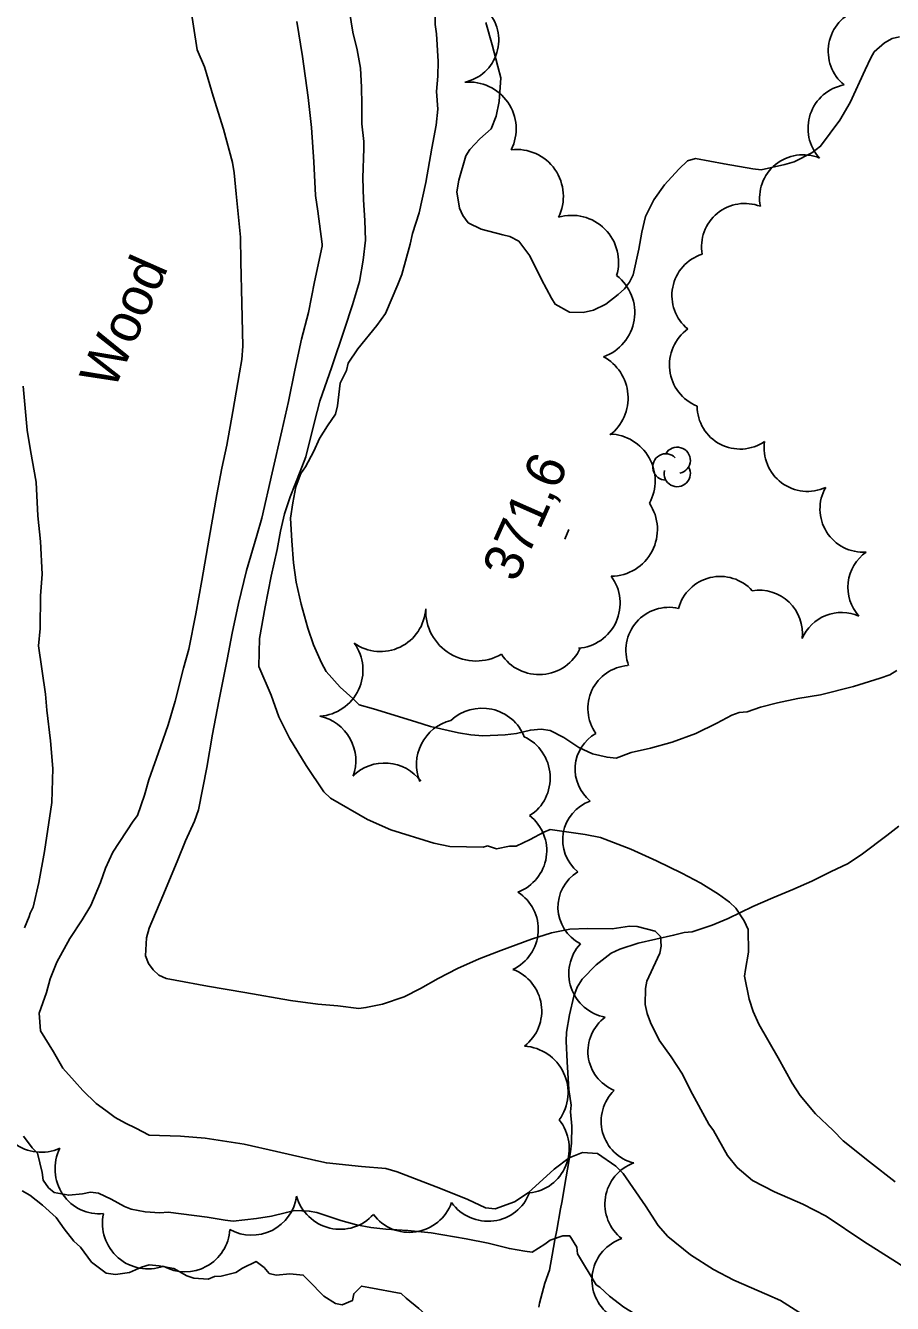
# Model space of a CAD drawing. Extents: x 287698 to 290158, y 5234163 to 5237182.
# Drawn here: x 288877.3 to 288944.5, y 5235304.2 to 5235403.1 of the extents above; entities that cross this region are included whole.
import ezdxf

# ---------------------------------------------------------------- set-up
doc = ezdxf.new("R2010")
doc.units = 0
for name, color, linetype in [('Niveau 1', 7, 'Continuous'), ('Niveau 2', 7, 'Continuous'), ('Niveau 3', 7, 'Continuous'), ('Niveau 4', 7, 'Continuous'), ('Niveau 44', 7, 'Continuous')]:
    doc.layers.add(name, color=color, linetype=linetype)

msp = doc.modelspace()

# ---------------------------------------------------------------- linework, layer by layer
at = {"layer": 'Niveau 1'}
for points in [[(288909.03, 5235404.38), (288909.07, 5235403.22), (288909.16, 5235402.51), (288909.29, 5235400.36), (288909.28, 5235399.23), (288909.16, 5235398.04), (288909.26, 5235396.66), (288909.13, 5235395.43), (288908.81, 5235393.65), (288908.33, 5235390.99), (288907.82, 5235388.64), (288907.3, 5235387.04), (288907.13, 5235386.21), (288906.49, 5235383.85), (288906.18, 5235383.08), (288905.23, 5235380.85), (288904.54, 5235379.92), (288903.08, 5235378.09), (288902.33, 5235377), (288902.2, 5235376.42), (288901.7, 5235375.44), (288901.7, 5235375.44)], [(288901.34, 5235373.04), (288901.51, 5235373.7), (288901.7, 5235375.44), (288901.7, 5235375.44)], [(288944.81, 5235353.19), (288944.27, 5235352.86), (288943.53, 5235352.59), (288941.47, 5235351.96), (288938.91, 5235351.31), (288937.16, 5235351.01), (288935.57, 5235350.68), (288934.26, 5235350.34), (288933.22, 5235349.98), (288932.62, 5235349.94), (288932.05, 5235349.72), (288930.89, 5235349.11), (288929.25, 5235348.32), (288927.42, 5235347.65), (288925.74, 5235347.17), (288924.25, 5235346.83), (288923.08, 5235346.4), (288922.38, 5235346.47), (288921.25, 5235346.73), (288920.2, 5235347.22), (288919.02, 5235347.99), (288917.98, 5235348.54), (288917.28, 5235348.64), (288916.44, 5235348.57), (288915.36, 5235348.31), (288914.49, 5235348.22), (288912.75, 5235348.14), (288911.82, 5235348.21), (288910.88, 5235348.37), (288908.71, 5235348.86), (288907.56, 5235349.22), (288904.28, 5235350.21), (288903.18, 5235350.54), (288902.7, 5235351.03), (288901.71, 5235351.9), (288900.63, 5235353.12), (288900.26, 5235353.78), (288899.63, 5235355.19), (288899.21, 5235356.48), (288898.68, 5235358.34), (288898.29, 5235360.03), (288898.09, 5235361.53), (288897.96, 5235363.22), (288897.87, 5235365), (288898.03, 5235366.17), (288898.27, 5235367.41), (288898.66, 5235368.46), (288899.01, 5235368.97), (288899.67, 5235370.17), (288900.11, 5235371.15), (288900.73, 5235372.14), (288901.34, 5235373.04)]]:
    msp.add_lwpolyline(points, dxfattribs=at)
at = {"layer": 'Niveau 2'}
for points in [[(288871.42, 5235442.49), (288871.8, 5235441.74), (288873.64, 5235438.07), (288875.41, 5235434.48), (288877.8, 5235431.27), (288880.18, 5235427.92), (288882.5, 5235424.24), (288884.58, 5235420.73), (288886.58, 5235416.8), (288888.1, 5235412.89), (288889.18, 5235408.93), (288890.06, 5235404.93), (288890.62, 5235401.27)], [(288902.27, 5235405.22), (288902.7, 5235402.62), (288903.03, 5235401.25), (288903.28, 5235399.83), (288903.37, 5235398.37), (288903.39, 5235397.03), (288903.39, 5235395.52)], [(288898.35, 5235403.46), (288898.78, 5235400.75), (288899.23, 5235397.58), (288899.49, 5235395.25), (288899.67, 5235392.59), (288899.8, 5235389.99), (288899.97, 5235388.76), (288900.32, 5235386.21), (288900.3, 5235386.06)], [(288945.02, 5235402.26), (288944.47, 5235402.13), (288943.86, 5235401.81), (288943.07, 5235401.1), (288942.8, 5235400.64), (288942.37, 5235399.7), (288941.2, 5235397.18), (288940.41, 5235395.82), (288938.91, 5235393.79), (288938.23, 5235393.28), (288936.87, 5235392.58), (288936.15, 5235392.39), (288934.31, 5235391.96), (288933.67, 5235392.05), (288931.44, 5235392.42), (288929.22, 5235392.84), (288928.62, 5235392.66), (288927.94, 5235392.03), (288926.83, 5235390.8), (288926, 5235389.63), (288925.36, 5235388.34), (288925.07, 5235387.13), (288924.84, 5235385.83), (288924.39, 5235383.84), (288924.12, 5235383.26), (288923.72, 5235382.74), (288923.24, 5235382.31), (288922.28, 5235381.55), (288921.32, 5235381.11), (288920.54, 5235380.92), (288919.47, 5235380.95), (288918.36, 5235381.55), (288918.08, 5235382.03), (288917.31, 5235383.46), (288916.4, 5235385.31), (288915.54, 5235386.43), (288914.85, 5235386.8), (288914.31, 5235386.92), (288912.62, 5235387.36), (288911.63, 5235387.87), (288911.22, 5235388.43), (288910.96, 5235388.99), (288910.75, 5235390.26), (288910.91, 5235391.17), (288911.43, 5235393.05), (288911.76, 5235393.54), (288912.53, 5235394.36), (288913.4, 5235395.14), (288913.8, 5235396.12), (288914.02, 5235397.26), (288914.14, 5235399.09), (288913.93, 5235399.98), (288913.49, 5235401.64), (288912.98, 5235403.37)], [(288890.62, 5235401.27), (288891.19, 5235399.94), (288891.36, 5235399.42), (288891.88, 5235397.66), (288892.66, 5235395.12), (288893.37, 5235392.54), (288893.49, 5235391.73), (288893.65, 5235390.1), (288893.98, 5235386.76), (288894.02, 5235384.83), (288894.09, 5235381.64), (288894.17, 5235378.32), (288894.09, 5235377.27), (288893.92, 5235376.24), (288893.39, 5235373.24), (288892.93, 5235370.65), (288892.55, 5235368.85), (288892.16, 5235366.81), (288891.57, 5235363.45), (288890.99, 5235360.17), (288890.53, 5235357.57), (288889.99, 5235354.84), (288889.58, 5235353.36), (288888.92, 5235350.82), (288888.38, 5235348.98), (288887.79, 5235347.28), (288886.9, 5235344.73), (288886.55, 5235343.53), (288886.02, 5235341.97), (288885.68, 5235341.51), (288884.09, 5235339.13), (288883.53, 5235337.89), (288883.14, 5235336.76), (288882.4, 5235334.98), (288881.73, 5235333.89), (288880.77, 5235332.43), (288879.76, 5235330.61), (288879.24, 5235329.3), (288878.95, 5235328.25), (288878.4, 5235326.64), (288878.4, 5235326.64)], [(288903.39, 5235395.52), (288903.53, 5235394.17), (288903.53, 5235393.62), (288903.46, 5235391.35), (288903.52, 5235389.64), (288903.63, 5235388.05), (288903.67, 5235386.52), (288903.5, 5235384.96), (288903.2, 5235383.32), (288902.66, 5235381.51), (288902.04, 5235379.62), (288901.05, 5235376.71), (288900.12, 5235374.05), (288899.72, 5235372.44), (288899.05, 5235369.74), (288898.62, 5235368.59), (288897.84, 5235366.64), (288897.39, 5235365.32), (288897.08, 5235363.99), (288896.83, 5235362.57), (288896.37, 5235360.49), (288895.9, 5235358.11), (288895.47, 5235355.67), (288895.4, 5235353.51), (288895.4, 5235353.51)], [(288900.3, 5235386.06), (288899.71, 5235383.29), (288899.25, 5235380.91), (288898.72, 5235378.85), (288898.19, 5235376.45), (288897.7, 5235374.02), (288897.18, 5235371.76), (288896.44, 5235368.51), (288895.63, 5235364.98), (288895.24, 5235363.64), (288894.46, 5235360.94), (288893.82, 5235358.37), (288893.33, 5235356.09), (288892.96, 5235354.05), (288892.32, 5235350.81), (288891.83, 5235348.26), (288891.38, 5235345.69), (288890.74, 5235342.41), (288890.43, 5235341.53), (288889.73, 5235340), (288889.08, 5235338.4), (288887.96, 5235335.73), (288886.91, 5235333.23), (288886.71, 5235332.48), (288886.64, 5235331.08), (288886.86, 5235330.5), (288887.22, 5235330), (288887.67, 5235329.6), (288888.24, 5235329.33), (288888.94, 5235329.2), (288891.44, 5235328.74), (288894.33, 5235328.25), (288897.87, 5235327.62), (288899.97, 5235327.35), (288901.53, 5235327.22), (288903.15, 5235327.01), (288903.7, 5235327.08), (288904.99, 5235327.36), (288906.67, 5235327.91), (288907.94, 5235328.57), (288909.29, 5235329.34), (288910.79, 5235330.12), (288912.46, 5235330.85), (288914.16, 5235331.51), (288916.53, 5235332.38), (288918.08, 5235332.88), (288919.5, 5235333.16), (288920.86, 5235333.2), (288922.77, 5235333.19), (288924.12, 5235333.38), (288924.72, 5235333.37), (288926.1, 5235333), (288926.51, 5235332.58), (288926.56, 5235331.84), (288926.46, 5235331.31), (288925.96, 5235330.2), (288925.46, 5235329.13), (288925.36, 5235328.55), (288925.32, 5235327.31), (288925.48, 5235326.62), (288925.75, 5235325.94), (288926.41, 5235324.57), (288927.34, 5235323.26), (288928.23, 5235321.92), (288928.83, 5235320.66), (288930.27, 5235318.06), (288930.61, 5235317.56)], [(288877.61, 5235334.14), (288877.7, 5235334.4), (288877.93, 5235334.87), (288878.36, 5235336.78), (288878.8, 5235339.16), (288879.37, 5235342.98), (288879.46, 5235345.6), (288879.27, 5235347.74), (288878.99, 5235350.11), (288878.88, 5235351.37), (288878.33, 5235355.09), (288878.47, 5235356.44), (288878.5, 5235358.98), (288878.63, 5235360.64), (288878.5, 5235363.18), (288878.3, 5235365.16), (288878.17, 5235367.77), (288877.72, 5235370.22), (288877.46, 5235371.8), (288877.16, 5235375.21)], [(288913.13, 5235339.61), (288912.79, 5235339.52), (288910.21, 5235339.57), (288908.96, 5235339.82), (288905.64, 5235340.84), (288903.82, 5235341.64), (288900.97, 5235343.29), (288900.43, 5235343.79), (288899.07, 5235345.83), (288897.78, 5235347.95), (288896.95, 5235349.6), (288896.36, 5235351.27), (288895.4, 5235353.51)], [(288944.7, 5235313.6), (288942.7, 5235315.13), (288940.67, 5235316.77), (288939.88, 5235317.56), (288938.52, 5235318.85), (288937.33, 5235320.28), (288936.71, 5235321.22), (288935.63, 5235323.18), (288934.14, 5235325.8), (288933.7, 5235326.77), (288933.39, 5235327.74), (288933.03, 5235329.51), (288933.1, 5235330.04), (288933.34, 5235331.38), (288933.32, 5235333.13), (288932.99, 5235333.8), (288932.34, 5235334.79), (288931.85, 5235335.26), (288931, 5235335.88), (288929.63, 5235336.73), (288928.18, 5235337.49), (288926.22, 5235338.45), (288924.22, 5235339.35), (288921.86, 5235340.25), (288920.67, 5235340.48), (288917.97, 5235340.88), (288917.49, 5235340.66), (288916.43, 5235340.09), (288915.35, 5235339.59), (288914.82, 5235339.58), (288913.81, 5235339.39), (288913.13, 5235339.61)], [(288877.27, 5235333.26), (288877.61, 5235334.14)], [(288938.86, 5235302.45), (288935.81, 5235304.39), (288934.75, 5235304.85), (288932.2, 5235305.97), (288930.62, 5235306.79), (288928.84, 5235307.93), (288927.09, 5235309.36), (288926.33, 5235310.21), (288925.35, 5235311.74), (288923.63, 5235314.24), (288923.06, 5235314.81), (288921.63, 5235315.78), (288920.48, 5235315.85), (288919.44, 5235315.44), (288918.29, 5235314.56), (288916.28, 5235312.73), (288915.21, 5235312.04), (288913.72, 5235311.5), (288912.96, 5235311.58), (288911.6, 5235312.23), (288909.48, 5235313.06), (288906.12, 5235314.37), (288905.24, 5235314.62), (288903.35, 5235314.78), (288900.64, 5235315.05), (288899.82, 5235315.24), (288896.77, 5235315.95), (288894.27, 5235316.51), (288891.24, 5235316.98), (288889.35, 5235317.12), (288886.92, 5235317.21), (288885.88, 5235317.74), (288885.07, 5235318.12), (288884.28, 5235318.58), (288883.55, 5235319.12), (288882.82, 5235319.66), (288881.77, 5235320.67), (288881.12, 5235321.38), (288880.23, 5235322.39), (288879.5, 5235323.65), (288878.51, 5235325.29), (288878.4, 5235326.64)], [(288921.53, 5235305.62), (288920.1, 5235308.02), (288920.03, 5235308.54), (288919.49, 5235309.4), (288918.96, 5235309.4), (288917.97, 5235309.08), (288917.57, 5235308.75), (288916.59, 5235308.15), (288916.01, 5235308.21), (288914.81, 5235308.42), (288913.16, 5235308.85), (288911.47, 5235309.17), (288908.75, 5235309.65), (288906.95, 5235309.81), (288905.24, 5235309.91), (288904.09, 5235310.05), (288902.97, 5235310.27), (288901.77, 5235310.6), (288899.9, 5235311.21), (288899.31, 5235311.32), (288898.16, 5235311.36), (288897.55, 5235311.22), (288896.4, 5235310.94), (288895.22, 5235310.76), (288893.41, 5235310.53), (288892.81, 5235310.61), (288891.4, 5235310.86), (288888.39, 5235311.23), (288887.74, 5235311.18), (288886.61, 5235311.26), (288885.51, 5235311.46), (288885, 5235311.69), (288883.96, 5235312.24), (288882.99, 5235312.71), (288882.37, 5235312.78), (288881.74, 5235312.65), (288880.69, 5235312.55), (288879.56, 5235312.75), (288879.12, 5235313.13), (288878.7, 5235313.71), (288878.62, 5235314.31), (288878.26, 5235315.82), (288877.84, 5235316.22), (288877.19, 5235317.13)], [(288950.21, 5235303.4), (288948.13, 5235304.97), (288945.94, 5235306.62), (288944.8, 5235307.36), (288942.27, 5235308.96), (288939.34, 5235310.93), (288937.53, 5235311.86), (288935.34, 5235312.82), (288933.63, 5235313.69), (288932.45, 5235314.7), (288931.71, 5235315.63), (288930.61, 5235317.56)], [(288942.75, 5235294.28), (288939.72, 5235295.28), (288936.11, 5235296.69), (288931.8, 5235298.73), (288930.28, 5235299.89), (288928.75, 5235300.97), (288927.71, 5235301.5), (288925.94, 5235302.49), (288923.69, 5235303.88), (288922.56, 5235304.73), (288921.83, 5235305.43), (288921.53, 5235305.62)]]:
    msp.add_lwpolyline(points, dxfattribs=at)
at = {"layer": 'Niveau 3'}
msp.add_line((288919.11, 5235363.37), (288919.43, 5235364.1), dxfattribs=at)
at = {"layer": 'Niveau 4'}
for points in [[(288944.98, 5235341.13), (288944.04, 5235340.4), (288942.17, 5235338.98), (288941.04, 5235338.23), (288939.69, 5235337.61), (288938.24, 5235336.87), (288936.77, 5235336.22), (288935.21, 5235335.58), (288933.67, 5235334.92), (288931.76, 5235333.99), (288930.53, 5235333.46), (288928.96, 5235332.95), (288928.34, 5235332.89), (288927.53, 5235332.69), (288924.78, 5235332.08), (288923.36, 5235331.62), (288922.7, 5235331.29), (288921.54, 5235330.39), (288920.45, 5235329.29), (288920.06, 5235328.67), (288919.81, 5235327.96), (288919.48, 5235326.53), (288919.24, 5235325.19), (288919.22, 5235324.47), (288919.28, 5235322.87), (288919.43, 5235320.73), (288919.59, 5235319.53), (288919.55, 5235319.01), (288919.64, 5235317.89), (288919.63, 5235316.58), (288919.54, 5235315.9), (288919.21, 5235313.97), (288918.87, 5235312), (288918.78, 5235311.49), (288918.49, 5235309.85), (288918.33, 5235309.09), (288918.13, 5235307.91), (288917.92, 5235306.76), (288917.56, 5235305.75), (288917.15, 5235304.2), (288917.09, 5235303.87)], [(288877.07, 5235312.88), (288877.66, 5235312.56), (288878.64, 5235311.79), (288879.71, 5235310.83), (288880.33, 5235309.95), (288881.07, 5235308.99), (288881.6, 5235308.53), (288882.45, 5235307.37), (288883.58, 5235306.52), (288884.3, 5235306.41), (288885.38, 5235306.57), (288886.33, 5235306.99), (288886.92, 5235307.15), (288887.68, 5235307.07), (288888.82, 5235306.87), (288889.84, 5235306.31), (288890.38, 5235306.13), (288891.48, 5235306.04), (288891.97, 5235306.26), (288892.48, 5235306.27), (288893.63, 5235306.57), (288894.15, 5235306.89), (288895.2, 5235307.41), (288895.81, 5235306.96), (288896.21, 5235306.48), (288896.75, 5235306.35)], [(288896.75, 5235306.35), (288897.81, 5235306.47), (288898.85, 5235306.36), (288899.26, 5235305.95), (288900.43, 5235304.74), (288901.34, 5235304.16), (288901.86, 5235304.07), (288902.67, 5235304.41), (288902.76, 5235304.92), (288903.37, 5235305.51), (288903.92, 5235305.41), (288906.42, 5235304.95), (288906.82, 5235304.57), (288907.8, 5235303.79), (288908.69, 5235303), (288909.3, 5235301.96), (288910.25, 5235300.52), (288911.12, 5235299.73), (288911.67, 5235299.63), (288912.95, 5235299.49), (288913.42, 5235299.39)]]:
    msp.add_lwpolyline(points, dxfattribs=at)
at = {"layer": 'Niveau 44'}
for centre, start, end in [((288927.809, 5235369.467), 282.26917, 149.72626), ((288926.931, 5235368.957), 44.11537, 269.80396), ((288927.809, 5235368.447), 166.93686, 29.62123)]:
    msp.add_arc(centre, 1.021, start, end, dxfattribs=at)
for centre, major_axis, ratio, start_param, end_param in [((288910.616, 5235402.027), (3.214, -1.031), 0.993097, 5.24029, 7.356426), ((288942.889, 5235401.153), (-3.329, 0.602), 0.999909, 5.215654, 7.344735), ((288911.699, 5235395.13), (3.203, 1.724), 0.999718, 5.330853, 7.4565), ((288941.365, 5235395.177), (-3.181, 1.268), 0.998652, 5.274768, 7.399038), ((288915.374, 5235389.92), (-2.075, 2.973), 0.998323, 3.637117, 5.787661), ((288937.553, 5235389.772), (-2.967, 1.585), 0.999188, 4.813067, 6.963214), ((288933.052, 5235386.004), (-3.054, 1.4), 0.999306, 4.777026, 6.884905), ((288919.655, 5235384.825), (-2.56, 2.56), 0.998332, 3.634846, 5.789932), ((288930.754, 5235382.235), (-3.34, -0.291), 0.999961, 4.932592, 7.081107), ((288920.915, 5235380.91), (0.579, 3.574), 0.998614, 3.636375, 5.788403), ((288930.651, 5235376.85), (-3.421, -0.408), 0.999802, 5.220506, 7.348), ((288920.395, 5235374.299), (0, 3.619), 0.99863, 3.799089, 5.79199), ((288932.702, 5235373.691), (-2.444, -2.3), 0.997566, 5.536247, 7.694833), ((288922.481, 5235367.886), (-2.775, 2.335), 0.998281, 3.339186, 5.376404), ((288937.905, 5235370.424), (2.689, -2.018), 0.999742, 3.637499, 5.787279), ((288942.221, 5235365.705), (3.146, -1.162), 0.999755, 2.975932, 5.134367), ((288922.663, 5235364.11), (1.68, 3.207), 0.999325, 3.634593, 5.790185), ((288944.392, 5235359.638), (-3.357, -0.112), 0.993314, 5.295515, 6.98071), ((288931.13, 5235357.166), (-3.239, -0.777), 0.993502, 3.633323, 5.791455), ((288919.951, 5235358.374), (1.444, 3.166), 0.986527, 3.634069, 5.790709), ((288934.189, 5235356.085), (-2.057, 2.631), 0.992081, 3.927691, 5.78793), ((288904.817, 5235358.185), (1.453, -3.217), 0.996289, 5.247251, 7.367353), ((288912.238, 5235357.837), (-2.005, -3.359), 0.999276, 5.218967, 7.344644), ((288927.167, 5235354.75), (-1.275, -3.081), 0.999088, 3.309392, 5.466278), ((288940.559, 5235354.369), (-3.328, -0.289), 0.991638, 4.216597, 5.792027), ((288899.897, 5235353.216), (3.232, -1.528), 0.999585, 5.222035, 7.347761), ((288917.117, 5235356.318), (3.482, 0.084), 0.988653, 3.690498, 5.842895), ((288924.238, 5235350.24), (-3.136, 1.164), 0.998517, 5.14756, 7.250616), ((288912.713, 5235346.888), (-3.451, 0.477), 0.970604, 3.636571, 5.620883), ((288899.511, 5235346.254), (-1.537, 3.128), 0.975417, 3.893611, 5.631401), ((288911.088, 5235345.942), (-1.807, -2.983), 0.99339, 3.924524, 5.653283), ((288914.584, 5235344.911), (-0.776, 3.385), 0.975002, 3.469231, 5.630962), ((288923.168, 5235345.545), (-3.226, 0.524), 0.983971, 5.406453, 7.319191), ((288905.144, 5235342.58), (-3.482, -0.173), 0.988685, 3.724792, 5.442681), ((288922.208, 5235340.055), (-3.226, 0.524), 0.983971, 5.223167, 7.319191), ((288914.169, 5235339.257), (3.507, -0.496), 0.977905, 5.229058, 7.316739), ((288921.954, 5235334.87), (-3.379, -0.141), 0.959188, 5.24563, 7.306358), ((288913.521, 5235333.149), (3.526, -0.212), 0.98122, 5.231335, 7.325118), ((288922.859, 5235329.722), (-3.26, -1.1), 0.999203, 5.221849, 7.34789), ((288913.756, 5235326.804), (3.531, 0.487), 0.976002, 5.252637, 7.336272), ((288924.311, 5235323.714), (-3.396, -0.376), 0.970853, 5.256775, 7.330766), ((288915.689, 5235320.465), (3.299, 1.62), 0.989585, 5.213612, 7.322249), ((288925.286, 5235318.29), (-3.242, -0.907), 0.993241, 5.21732, 7.328815), ((288878.512, 5235319.318), (3.22, -1.343), 0.981656, 3.384778, 5.539743), ((288916.022, 5235316.205), (-0.967, 3.347), 0.98332, 2.957422, 5.111105), ((288882.993, 5235314.607), (0.09, -3.489), 0.964681, 4.216856, 6.371764), ((288925.625, 5235311.862), (-3.377, 0.507), 0.994923, 5.215279, 7.338053), ((288894.871, 5235312.901), (3.401, 0.756), 0.988138, 3.982963, 5.938153), ((288901.654, 5235313.348), (2.902, -1.924), 0.980891, 3.992598, 6.150849), ((288913.122, 5235313.992), (2.63, -2.289), 0.986264, 4.485041, 6.635864), ((288907.065, 5235313.149), (1.459, 3.158), 0.996793, 2.644785, 4.801112), ((288886.743, 5235310.314), (2.082, -2.806), 0.979446, 3.855324, 6.008229), ((288889.689, 5235310.104), (1.744, -3.014), 0.999867, 5.251904, 7.267801), ((288924.576, 5235305.995), (-3.244, 0.899), 0.999358, 5.301679, 7.425141)]:
    msp.add_ellipse(centre, major_axis=major_axis, ratio=ratio, start_param=start_param, end_param=end_param, dxfattribs=at)

# ---------------------------------------------------------------- texts
at = {"layer": 'Niveau 3'}
msp.add_text('371,6', height=3, rotation=66.1217, dxfattribs=at).set_placement((288915.35, 5235359.93))
at = {"layer": 'Niveau 44'}
msp.add_text('Wood', height=3, rotation=66.1217, dxfattribs=at).set_placement((288884.18, 5235374.82))

doc.saveas('drawing.dxf')
